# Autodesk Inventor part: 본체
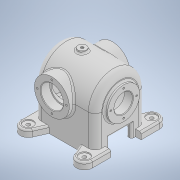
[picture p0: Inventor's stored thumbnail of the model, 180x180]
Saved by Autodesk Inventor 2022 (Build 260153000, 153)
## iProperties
Created: 2024-09
Part Number: 본체
Material: 일반
Document SubType Name: Modeling
Designer: PC-12
Density: 1 g/cm^3
Appearance: 기본값
Author: PC-12
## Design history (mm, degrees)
sketch "스케치1"
  geometry: L1 (-45, 45)-(45, 45); L2 (45, 45)-(45, -45); L3 (45, -45)-(-45, -45); L4 (-45, -45)-(-45, 45); L5 (-45, 45)-(45, -45); L6 (45, 45)-(-45, -45); 1 further point
  constraints: 12 end point, 2 midpoint, 2 parallel, 1 horizontal, 1 perpendicular
  dimensions: "d0" = 90 distance of L1.end L2.end; "d1" = 90 distance of L1.start L1.end
extrude "돌출1" new body sketch "스케치1" distance "d2" = 108; taper "d3" = 0 deg
sketch "스케치2"
  geometry: L1 (0, -45)-(0, 45) reference; L2 (0, 45)-(108, 45) reference; L3 (108, -45)-(108, 45) reference; L4 (0, -45)-(108, -45) reference; L5 (0, 0)-(-30.111, 0); L6 (9, 0)-(9, 36); L7 (9, 36)-(99, 36); L8 (99, 36)-(99, 16.5); L9 (99, 16.5)-(108, 16.5); L10 (108, 16.5)-(114, 16.5); L11 (114, 16.5)-(114, 0); L12 (114, 0)-(9, 0); L13 (114, 16.5)-(114, 28.5); L14 (114, 28.5)-(108, 28.5); L15 (108, 28.5)-(108, 16.5); 1 further point
  constraints: 22 end point, 5 perpendicular, 2 horizontal, 2 point on line, 2 vertical, 1 collinear, 1 horizontal alignment, 1 midpoint, 1 parallel
  dimensions: "d4" = 9 distance between parallel lines of L1 L6; "d6" = 9 distance between parallel lines of L3 L8; "d8" = 72 diameter of L7 L5; "d9" = 33 diameter of L9 L5; "d10" = 57 diameter of L14 L5; "d11" = 6 distance of L13.end L14.end; "d12" = 105 distance of L11.end L6.start (derived)
  node "투영된 루프1"
revolve "회전1" stored, may be unused: angle "d13" = 90 deg
revolve "회전2" stored, may be unused: angle "d14" = 90 deg
node "작업 평면1"
fillet "모깎기3" dims "d48" = 45
fillet "모깎기4" dims "d49" = 12
fillet "모깎기5" dims "d50" = 12
node "작업 평면3"
sketch "스케치5"
  geometry: L1 (114, -28.5)-(114, 28.5) reference; C1 r 31 at (40, 0); C2 r 20 at (40, 0); C3 r 17.5 at (40, 0); 1 further point
  constraints: 3 centre point, 1 horizontal alignment
  dimensions: "d52" = 62 diameter of C1; "d53" = 74 distance from line of L1 C1.centre; "d54" = 40 diameter of C2; "d55" = 35 diameter of C3
extrude "돌출2" join sketch "스케치5" stored distance "d56" = 108; taper "d57" = 0 deg
extrude "돌출3" cut sketch "스케치5" distance "d58" = 16; taper "d59" = 0 deg
extrude "돌출4" cut sketch "스케치5" extent not by distance; stored distance "d60" = 0; taper "d61" = 0 deg
node "작업 평면4"
sketch "스케치6"
  geometry: L1 (108, 66)-(108, 0) reference; L2 (12, 78)-(96, 78) reference; L3 (0, 66)-(0, 0) reference; L4 (12, -12)-(96, -12) reference; L5 (0, 53)-(108, 53); L6 (108, 53)-(108, 13); L7 (108, 13)-(0, 13); L8 (0, 13)-(0, 53); L9 (0, 53)-(108, 13); L10 (108, 53)-(0, 13); L11 (108, 53)-(9, 53); L12 (9, 53)-(9, 69); L13 (9, 69)-(99, 69); L14 (99, 69)-(99, 53); A1 r 12 centre (96, 0) between (96, -12) and (108, 0) reference; A2 r 12 centre (96, 66) between (108, 66) and (96, 78) reference; A3 r 12 centre (12, 66) between (12, 78) and (0, 66) reference; A4 r 12 centre (12, 0) between (0, 0) and (12, -12) reference; A5 r 12 centre (96, 66) between (108, 66) and (96, 78) reference; 9 further points
  constraints: 20 end point, 6 midpoint, 3 parallel, 3 perpendicular, 2 coincident, 2 horizontal, 1 point on line
  dimensions: "d63" = 40 distance of L5.end L6.end; "d64" = 9 distance between parallel lines of L2 L13; "d65" = 9 distance between parallel lines of L3 L12; "d66" = 9 distance between parallel lines of L1 L14
extrude "돌출5" join sketch "스케치6" stored distance "d67" = 10; taper "d68" = 0 deg
sketch "스케치7"
  geometry: L1 (99, 13)-(108, 13) reference; L2 (108, 53)-(108, 13) reference; L3 (108, 53)-(99, 53) reference; L4 (99, 53)-(99, 69) reference; L5 (99, 69)-(9, 69) reference; L6 (9, 69)-(9, 53) reference; L7 (9, 53)-(0, 53) reference; L8 (0, 53)-(0, 13) reference; L9 (0, 13)-(9, 13) reference; L10 (9, 13)-(9, -3) reference; L11 (9, -3)-(99, -3) reference; L12 (99, -3)-(99, 13) reference; L13 (0, 66)-(0, 53) reference; L14 (0, 53)-(9, 53) reference; L15 (9, 53)-(9, 69) reference; L16 (9, 69)-(99, 69) reference; L17 (99, 69)-(99, 53) reference; L18 (99, 53)-(108, 53) reference; L19 (108, 53)-(108, 66) reference; L20 (96, 78)-(12, 78) reference; L21 (9, 69)-(99, 69) reference; L22 (54, 69)-(54, 97.77); L23 (-10, 93)-(-10, 60); L24 (16.79, 98.693)-(26, 78); L25 (-10, 60)-(0, 60); L26 (0, 66)-(0, 53) reference; L27 (-10, -27)-(-10, 6); L28 (71, -12)-(12, -12) reference; L29 (26, -12)-(16.79, -32.693); L30 (-10, 6)-(0, 6); L31 (0, 0)-(0, 13) reference; A1 r 14 centre (4, 93) between (16.79, 98.693) and (-10, 93); A2 r 14 centre (4, -27) between (-10, -27) and (16.79, -32.693); A3 r 12 centre (96, 66) between (108, 66) and (96, 78) reference; A4 r 12 centre (12, 66) between (12, 78) and (0, 66) reference; A5 r 12 centre (12, 0) between (0, 0) and (12, -12) reference; 3 further points
  constraints: 14 end point, 4 point on circle, 4 point on line, 4 tangent, 3 vertical, 2 centre point, 2 horizontal, 1 midpoint, 1 vertical alignment
  dimensions: "d69" = 120 distance of A2.centre A1.centre; "d70" = 60 vertical distance of point (0, 33) A1.centre; "d71" = 28 diameter of A1; "d72" = 28 diameter of A2; "d73" = 148 dimension on A2 A1 (derived); "d75" = 50 horizontal distance of L22.end A1.centre; "d76" = 36 distance from line of L24.end L23; "d77" = 18 distance from line of L20 L23.end; "d78" = 36 horizontal distance of L29.start L27.end; "d79" = 18 distance from line of L27.end L28
extrude "돌출6" join sketch "스케치7" distance "d80" = 12; taper "d81" = 0 deg
node "작업 평면5"
sketch "스케치8"
  geometry: L1 (-10, -60)-(-10, -93) reference; L2 (118, -60)-(118, -93) reference; L3 (12, -75.988)-(12, 9.988) reference; L4 (71, -78)-(96, -78) reference; L5 (96, 12)-(96, -78) reference; L6 (96, 12)-(71, 12) reference; L7 (108, -4.5)-(108, -61.5) reference; L8 (114, -61.5)-(114, -4.5) reference; L9 (114, -49.5)-(114, -16.5) reference; L10 (0, -33)-(108, -33); L11 (54, -33)-(54, -40.769); C1 r 9 at (4, -93); C2 r 9 at (104, -93); A1 r 14 centre (4, -93) between (-10, -93) and (16.79, -98.693) reference; A2 r 14 centre (104, -93) between (91.21, -98.693) and (118, -93) reference; 1 further point
  constraints: 4 end point, 3 coincident, 2 centre point, 2 midpoint, 1 vertical, 2 other
  dimensions: "d86" = 18 diameter of C1; "d87" = 18 diameter of C2
extrude "돌출7" cut sketch "스케치8" distance "d88" = 2; taper "d89" = 0 deg
sketch "스케치9"
  geometry: C1 r 9 at (0, 0) reference; C2 r 9 at (100, 0) reference; 3 further points
  constraints: 2 coincident
hole "구멍1" sketch "스케치9" at (0, 0), (100, 0) diameter "d90" = 6.6; stored, may be unused: countersink angle "d94" = 90 deg, drill point angle "d96" = 0 deg; dims "d91" = 6, "d92" = 8, "d93" = 2, "d95" = 17.1
node "작업 평면7"
sketch "스케치11"
  geometry: L1 (-114, 28.5)-(-114, -28.5) reference; C1 r 7.5 at (-40, 0); 1 further point
  constraints: 1 centre point, 1 horizontal alignment
  dimensions: "d99" = 15 diameter of C1; "d100" = 74 distance from line of L1 C1.centre
extrude "돌출8" join sketch "스케치11" stored distance "d101" = 108; taper "d102" = 0 deg
sketch "스케치12"
  geometry: C1 r 7.5 at (0, 0) reference; 2 further points
  constraints: 1 coincident
hole "구멍2" sketch "스케치12" at (0, 0) diameter "d103" = 4.917; stored, may be unused: countersink angle "d107" = 90 deg, drill point angle "d109" = 0 deg; dims "d104" = 12, "d105" = 4, "d106" = 2, "d108" = 8
sketch "스케치13"
  geometry: C1 r 20 at (0, 0) reference; C2 r 31 at (0, 0) reference; 2 further points
  constraints: 1 vertical alignment
  dimensions: "d110" = 26 distance of C1.centre point (0, 26)
hole "구멍3" sketch "스케치13" at (0, 26) diameter "d111" = 3.242; stored, may be unused: countersink angle "d115" = 90 deg, drill point angle "d117" = 118 deg; dims "d112" = 8, "d113" = 4, "d114" = 2, "d116" = 10
sketch "스케치14"
  geometry: C1 r 28.5 at (0, 0) reference; C2 r 16.5 at (0, 0) reference; 2 further points
  constraints: 1 vertical alignment
  dimensions: "d121" = 23 distance of point (0, 0) point (0, 23)
hole "구멍4" sketch "스케치14" at (0, 23) diameter "d122" = 3.242; stored, may be unused: countersink angle "d126" = 90 deg, drill point angle "d128" = 118 deg; dims "d123" = 8, "d124" = 4, "d125" = 2, "d127" = 10
fillet "모깎기6" dims "d132" = 3
chamfer "모따기1" distance "d133" = 1; stored, may be unused: second distance "d134" = 2, angle "d135" = 45 deg
sketch "스케치15"
  geometry: C1 r 7.5 at (0, 0) reference; 2 further points
  constraints: 1 coincident
hole "구멍5" sketch "스케치15" at (0, 0) diameter "d136" = 3.242; stored, may be unused: countersink angle "d140" = 90 deg, drill point angle "d142" = 118 deg; dims "d137" = 8, "d138" = 4, "d139" = 2, "d141" = 10
node "솔리드1"
mirror "미러1"
mirror "미러2"
mirror "미러3"
mirror "미러4"
mirror "미러5"
pattern_circular "원형 패턴1" dims angle "d119" = 360 deg
mirror "미러6"
pattern_circular "원형 패턴2" dims angle "d130" = 360 deg
node "투영된 루프5"
node "투영된 루프6"
node "투영된 루프7"
node "투영된 루프8"
node "투영된 루프9"
node "투영된 루프10"
node "투영된 루프11"
node "투영된 루프14"
node "투영된 루프15"
node "투영된 루프16"
node "투영된 루프17"
feature "A9D066F2-1C7D-4E18-AEED-F7BC21143FA4" dims "d90" = 6.6, "d91" = 6, "d92" = 8, "d93" = 2, "d94" = 90 deg, "d95" = 17.1, "d96" = 0
other parameters: "d16" = 34, "d51" = -54, "d62" = 23, "d82" = -54, "d98" = 49
